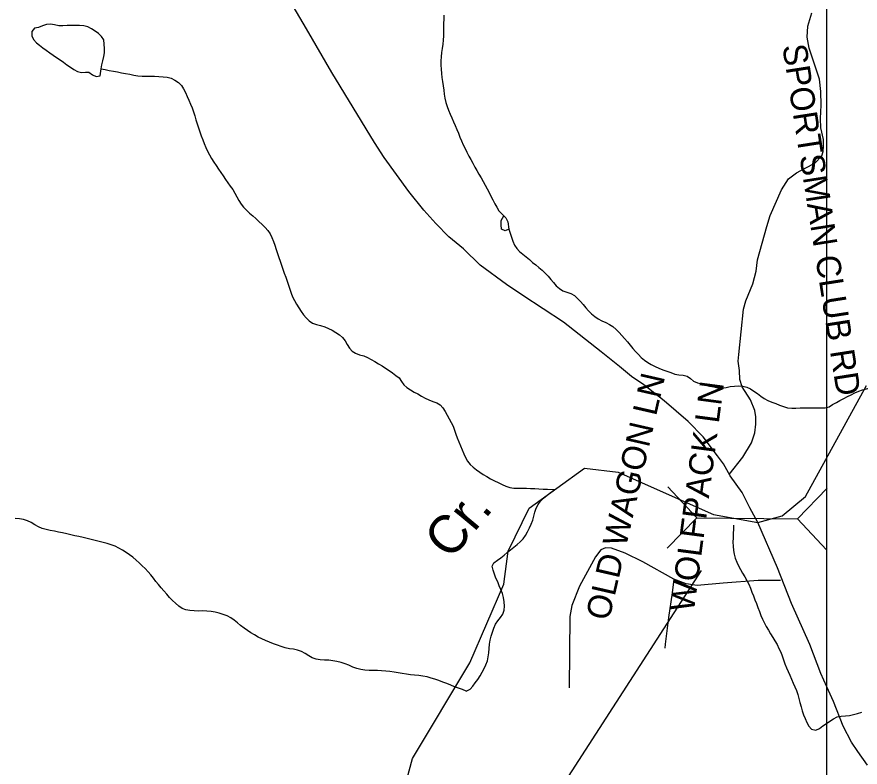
# Model space of a CAD drawing. Extents: x 1950930 to 2061844, y 904556 to 1017002.
# Drawn here: x 1987086 to 1990402, y 964344 to 967294 of the extents above; entities that cross this region are included whole.
import ezdxf

# ---------------------------------------------------------------- set-up
doc = ezdxf.new("R2010")
doc.units = 0
for name, color, linetype in [('Exist Cultural Church Label', 7, 'Continuous'), ('Exist Hydrographic Creek Single Shore', 7, 'Continuous'), ('Exist Hydrographic Creek Single Shore Label', 7, 'Continuous'), ('Exist Hydrographic Misc Water Feature', 7, 'Continuous'), ('Exist Road Non-System Type 51', 7, 'Continuous'), ('Exist Road Non-System Type 51 Label', 7, 'Continuous'), ('Exist Road Primary NC Attributed', 7, 'Continuous'), ('Exist Road Primary NC Structure Culvert Number Label', 7, 'Continuous'), ('Map Preparation Inset Cut Line', 7, 'Continuous')]:
    doc.layers.add(name, color=color, linetype=linetype)

msp = doc.modelspace()

# ---------------------------------------------------------------- linework, layer by layer
at = {"layer": 'Exist Cultural Church Label'}
for p, q in [((1989645.5, 965446.5), (1989758.9, 965324.5)), ((1990271.3, 965440.7), (1990155.7, 965320.9)), ((1989643.3, 965204.7), (1989758.9, 965324.5)), ((1989758.9, 965324.5), (1990155.7, 965320.9)), ((1990269.1, 965198.9), (1990155.7, 965320.9))]:
    msp.add_line(p, q, dxfattribs=at)
at = {"layer": 'Exist Hydrographic Creek Single Shore'}
msp.add_lwpolyline([(1988575.5, 964136.3), (1988641.5, 964377.7), (1988866.4, 964753.8), (1989000.3, 965062.9), (1989017.4, 965193.8), (1989100.4, 965362.7), (1989317.4, 965519), (1989450.4, 965503.1), (1989825.5, 965337.8), (1989998.7, 965305.8), (1990094.9, 965332.7), (1990186.4, 965408.4), (1990426.5, 965844)], dxfattribs=at)
at = {"layer": 'Exist Hydrographic Misc Water Feature'}
for points in [[(1988764.9, 967300.7), (1988764.3, 967284.3), (1988763.9, 967267.9), (1988763.7, 967251.5), (1988763.2, 967235), (1988762.8, 967218.7), (1988762, 967202.3), (1988760.4, 967185.9), (1988758.3, 967169.6), (1988755.9, 967153.2), (1988754, 967136.8), (1988753, 967120.4), (1988753.2, 967104), (1988754, 967087.6), (1988755.5, 967071.1), (1988757.5, 967055.5), (1988759.8, 967039.1), (1988762, 967022.5), (1988764.1, 967006.1), (1988766.3, 966989.6), (1988769, 966974.1), (1988772.7, 966957.5), (1988777.6, 966941.9), (1988783.3, 966927), (1988789.5, 966911.3), (1988796.1, 966896.3), (1988802.6, 966881.5), (1988809.2, 966866.5), (1988815.3, 966850.8), (1988821.9, 966835.8), (1988828.2, 966821), (1988834.6, 966806.1), (1988841.4, 966790.4), (1988848.1, 966775.5), (1988855.7, 966761.4), (1988863.1, 966746.4), (1988870.9, 966732.3), (1988878.7, 966718.3), (1988886.7, 966703.3), (1988894.7, 966689.2), (1988902.9, 966675.1), (1988910.9, 966660.9), (1988918.9, 966646), (1988927.1, 966631.9), (1988934.9, 966617.8), (1988942.5, 966602.8), (1988950, 966588.8), (1988957.4, 966573.8), (1988964.8, 966558.9), (1988972.6, 966544.9), (1988981, 966530.7), (1989000.1, 966511.4)], [(1987416.9, 967089), (1987420.2, 967105.3), (1987423.6, 967120.9), (1987428.4, 967137.2), (1987430.8, 967152.7), (1987430, 967169.2), (1987429.4, 967186.4), (1987427.3, 967202.8), (1987419.3, 967216.1), (1987407.6, 967227.8), (1987394.1, 967238), (1987379.8, 967246.5), (1987365.4, 967254.2), (1987349.6, 967258.6), (1987332.6, 967259.8), (1987316.2, 967260.1), (1987300, 967259.7), (1987283.4, 967259.2), (1987267, 967258.7), (1987250.6, 967259), (1987234.4, 967261.7), (1987218, 967264.6), (1987202, 967264.1), (1987186.6, 967258.7), (1987171.6, 967251.6), (1987154.8, 967248.6), (1987145.2, 967235.8), (1987144.8, 967219.3), (1987151.7, 967204.4), (1987163, 967191.9), (1987175.5, 967181.8), (1987188.4, 967171.6), (1987201.6, 967162.4), (1987215.1, 967152.2), (1987228.6, 967142.9), (1987242, 967133.7), (1987255.9, 967124.4), (1987269.4, 967115), (1987283, 967105.7), (1987296.3, 967095.5), (1987309.8, 967086.2), (1987324.2, 967078.5), (1987340.4, 967075), (1987356.2, 967075.6), (1987369.5, 967076.8), (1987382.8, 967065.9), (1987398, 967059), (1987413.6, 967062), (1987416.9, 967089)], [(1987416.9, 967089), (1987432.9, 967086.2), (1987449.1, 967083.3), (1987465.3, 967080.7), (1987481.3, 967077), (1987497.5, 967074.2), (1987513.5, 967071.4), (1987529.9, 967068.6), (1987545.9, 967065), (1987562.1, 967062.2), (1987578.3, 967060.2), (1987594.4, 967059.9), (1987611.1, 967060.4), (1987627.5, 967060.8), (1987643.9, 967059.7), (1987660.7, 967058.5), (1987677.1, 967056.5), (1987692.5, 967052.1), (1987707.6, 967045.2), (1987721.6, 967035.9), (1987732.9, 967024.2), (1987741.7, 967010.9), (1987749.5, 966996.8), (1987756.2, 966981.1), (1987762.6, 966966.2), (1987768.7, 966950.5), (1987774.9, 966935.5), (1987780.2, 966919.8), (1987785.1, 966904.1), (1987789.9, 966888.4), (1987794.6, 966872.8), (1987799.7, 966857.1), (1987805.4, 966841.4), (1987811, 966826.5), (1987816.7, 966810.7), (1987822.9, 966795.9), (1987829, 966780.2), (1987836, 966765.3), (1987843.2, 966751.2), (1987851.6, 966737), (1987860.4, 966722.9), (1987869.6, 966709.5), (1987878.9, 966695.5), (1987887.9, 966682.2), (1987897.3, 966668.8), (1987906.5, 966654.7), (1987916, 966641.4), (1987925.2, 966628), (1987934.6, 966614.7), (1987943, 966600.6), (1987951.2, 966586.4), (1987959, 966571.5), (1987967.6, 966557.4), (1987977.3, 966544.9), (1987988.8, 966533.2), (1988001.1, 966522.2), (1988013.6, 966511.4), (1988025.7, 966500.4), (1988037.8, 966488.7), (1988050.1, 966477.7), (1988062, 966466), (1988072.6, 966453.5), (1988081.4, 966440.2), (1988088.6, 966426.1), (1988095, 966410.4), (1988100.7, 966395.5), (1988105.6, 966379), (1988110.8, 966363.2), (1988116.1, 966347.5), (1988121.6, 966332.7), (1988127, 966317), (1988132.3, 966301.3), (1988137.6, 966285.6), (1988143.2, 966270.7), (1988148.5, 966255), (1988153.8, 966239.4), (1988158.8, 966223.7), (1988164.1, 966208), (1988170, 966193), (1988177.2, 966178.1), (1988185.4, 966164), (1988194.2, 966149.8), (1988203.2, 966135.7), (1988213.3, 966121.6), (1988224, 966109.9), (1988235.2, 966098.2), (1988248.4, 966089.7), (1988263.7, 966084.4), (1988280.3, 966080.8), (1988296.8, 966075.5), (1988311.5, 966068.6), (1988326.3, 966061.8), (1988340.6, 966053.3), (1988354, 966044), (1988366.3, 966033.1), (1988376.5, 966020.6), (1988385.1, 966005.6), (1988393.9, 965991.5), (1988404.6, 965979.8), (1988417.9, 965971.3)], [(1989020.4, 966458.5), (1989006.2, 966452.2), (1988991.9, 966459.1), (1988990.6, 966476.3), (1988990.4, 966492.8), (1989000.1, 966511.4)], [(1989000.1, 966511.4), (1989009.1, 966503), (1989016.3, 966487.3), (1989020.4, 966458.5)], [(1989020.4, 966458.5), (1989025.7, 966442.8), (1989030.8, 966427.1), (1989036.4, 966411.4), (1989042.7, 966396.5), (1989051.3, 966383.2), (1989062.6, 966371.4), (1989075.1, 966360.5), (1989088.3, 966350.4), (1989101, 966339.5), (1989113.5, 966328.6), (1989126.4, 966318.4), (1989138.9, 966308.4), (1989151.4, 966297.4), (1989163.5, 966286.5), (1989174.8, 966273.9), (1989185.2, 966261.5), (1989195.9, 966248.9), (1989207, 966236.4), (1989218.9, 966225.4), (1989232.6, 966216.9), (1989248.4, 966211.7), (1989264.2, 966206.4), (1989278.1, 966197.9), (1989290.2, 966187.1), (1989301.5, 966175.3), (1989312.6, 966162.9), (1989323.2, 966150.3), (1989334.1, 966137.7), (1989345.6, 966126.1), (1989357.9, 966115.1), (1989371.4, 966106.7), (1989386, 966099), (1989401.4, 966092), (1989415.9, 966084.4), (1989429.7, 966075.9), (1989442, 966065), (1989453.7, 966053.2), (1989464.7, 966041.5), (1989475.6, 966029), (1989486.3, 966015.6), (1989496.9, 966003), (1989507.6, 965990.5), (1989518.2, 965978), (1989529.5, 965966.3), (1989541.2, 965954.5), (1989553.5, 965944.5), (1989566.6, 965934.3), (1989580.4, 965926.6), (1989595.1, 965919), (1989610.3, 965912.1), (1989625.9, 965906), (1989641.5, 965900.8), (1989657.3, 965895.6), (1989672.9, 965889.5), (1989688.6, 965885.8), (1989705.3, 965884.7), (1989721.3, 965881.1), (1989734.4, 965871.8), (1989746.9, 965860.9), (1989761.9, 965854.8), (1989777.6, 965850.5), (1989793.6, 965846), (1989809.6, 965842.4), (1989825.8, 965838.8), (1989842, 965835.1), (1989858, 965834), (1989874.2, 965836.1), (1989890.6, 965839.9), (1989907, 965842), (1989923.2, 965842.5), (1989940.2, 965842.2), (1989955.8, 965837.7), (1989970.2, 965830.8), (1989984.1, 965822.3), (1989997.9, 965813), (1990011.4, 965802.9), (1990024.7, 965793.7), (1990039.1, 965785.2), (1990054, 965779.1), (1990069.8, 965773.8), (1990085, 965767.7), (1990100.6, 965761.7), (1990116.4, 965757.3), (1990132.4, 965755.2), (1990148.8, 965754.9), (1990165.2, 965756.3), (1990181.8, 965756.7), (1990198.2, 965757.2), (1990214.8, 965756.9), (1990231.4, 965756.6), (1990247.8, 965756.1), (1990264, 965756.7), (1990279.6, 965760.5), (1990293.3, 965769.2), (1990308.1, 965777.9), (1990322.3, 965785.8), (1990336.8, 965792.9), (1990351.6, 965800.8), (1990366.1, 965807.9)], [(1988417.9, 965971.3), (1988433.5, 965965.2), (1988449.7, 965960.8), (1988465.1, 965954.7), (1988479.5, 965947.1), (1988493.8, 965938.5), (1988507.8, 965930), (1988521.9, 965921.5), (1988535.6, 965912.3), (1988549.4, 965903.8), (1988563.1, 965893.6), (1988576.2, 965884.3), (1988588.7, 965874.2), (1988598, 965860.8), (1988607.2, 965846.8), (1988619.5, 965836.7), (1988633.4, 965827.4), (1988647.8, 965818.8), (1988662.2, 965811.2), (1988676.5, 965802.7), (1988690.9, 965795), (1988705.6, 965788.1), (1988721.6, 965782.1), (1988737.2, 965776.9), (1988750.9, 965768.3), (1988761.4, 965756.7), (1988769.6, 965742.5), (1988777.4, 965727.5), (1988786, 965713.4), (1988794.2, 965699.3), (1988801.4, 965684.4), (1988806.9, 965668.7), (1988812.3, 965653), (1988817.8, 965638.1), (1988824.1, 965622.4), (1988830.5, 965607.5), (1988836.7, 965591.7), (1988843, 965576), (1988850, 965561.1), (1988858.4, 965547), (1988868.6, 965534.5), (1988880.3, 965523.5), (1988892.8, 965513.5), (1988906, 965504.1), (1988919.9, 965494.9), (1988934.3, 965486.4), (1988948.8, 965477.9), (1988963.8, 965470.2), (1988978.3, 965462.5), (1988993.5, 965455.6), (1989008.3, 965448.8), (1989023.7, 965443.4), (1989039.9, 965441.5), (1989056.5, 965441.2), (1989073.3, 965440.8), (1989089.9, 965440.5), (1989106.1, 965439.3), (1989122.5, 965439), (1989138.9, 965437.8), (1989155.5, 965437.5), (1989171.7, 965437.1), (1989201, 965435.7)], [(1990366.1, 965807.9), (1990380.9, 965815), (1990395.9, 965822), (1990411.3, 965827.4), (1990427.2, 965831.2), (1990445.9, 965836.5)], [(1988852.9, 964642.9), (1988868, 964650.8), (1988879.1, 964662.1), (1988888.5, 964675), (1988897.8, 964688.7), (1988907, 964703.3), (1988915.4, 964717.1), (1988923.4, 964731.7), (1988930.2, 964746.4), (1988936.1, 964761.8), (1988939.4, 964777.3), (1988941.4, 964793.7), (1988942.7, 964810.1), (1988944.1, 964827.3), (1988946.8, 964842.8), (1988951.1, 964859.1), (1988955.8, 964874.6), (1988961.7, 964890.1), (1988968.1, 964905.6), (1988977.1, 964919.3), (1988987.6, 964932.2), (1988996.6, 964946), (1989001.5, 964960.6), (1989002.7, 964977.1), (1989001.7, 964994.3), (1988999.5, 965010.8), (1988995.4, 965026.4), (1988989.4, 965042.2), (1988982.9, 965057), (1988976.5, 965072), (1988969.7, 965086.9), (1988963.6, 965102.6), (1988958.3, 965118.3), (1988954.8, 965134.8), (1988961.5, 965147.8), (1988976.1, 965157.3), (1988989.2, 965167.6), (1989001.7, 965178.1), (1989014.2, 965188.5), (1989026.7, 965198.9), (1989039.7, 965209.3), (1989053, 965219.6), (1989065.5, 965230.1), (1989076.8, 965241.4), (1989086.2, 965255.1), (1989094.2, 965268.9), (1989101.4, 965284.3), (1989107.9, 965299), (1989114.1, 965314.5), (1989118.6, 965330.8), (1989123.1, 965347.1), (1989128.2, 965362.6), (1989135.4, 965376.4), (1989145.3, 965389.3), (1989156.7, 965401.4), (1989169.5, 965411.8), (1989182.4, 965422.1), (1989201, 965435.7)], [(1987393.9, 965235.1), (1987377.7, 965238.8), (1987361.9, 965243.2), (1987346.1, 965246.8), (1987329.7, 965250.5), (1987313.9, 965254.1), (1987298.1, 965257.7), (1987282, 965261.3), (1987266, 965264.9), (1987249.8, 965268.5), (1987233.8, 965271.3), (1987217.4, 965274.1), (1987201.4, 965277.8), (1987185.8, 965282.2), (1987170.6, 965288.2), (1987156.5, 965296.7), (1987142.5, 965306.1), (1987128, 965312.9), (1987112.2, 965317.3), (1987096, 965320.1), (1987079.8, 965322.1)], [(1989903.1, 965295.6), (1989903.1, 965279.2), (1989902.7, 965262.8), (1989902.1, 965245.7), (1989901.5, 965229.2), (1989901.9, 965212.8), (1989903.1, 965196.4), (1989906, 965180.8), (1989910.3, 965165.1), (1989916.3, 965150.1), (1989923.2, 965135.2), (1989931.2, 965121.1), (1989939.4, 965106.1), (1989947.8, 965092.1), (1989955.8, 965077.9), (1989963.4, 965063), (1989970, 965048.1), (1989976.3, 965032.3), (1989982.3, 965017.4), (1989988, 965001.8), (1989993.8, 964986.9), (1989999.5, 964971.2), (1990005.5, 964956.3), (1990011.6, 964940.7), (1990018.2, 964925.7), (1990025.1, 964910.8), (1990032.5, 964896.7), (1990040.7, 964882.5), (1990049.5, 964868.4), (1990058.2, 964854.3), (1990066.8, 964840.2), (1990075, 964826), (1990082.3, 964811.1), (1990089.1, 964796.2), (1990094.9, 964781.3), (1990100.4, 964765.6), (1990105.7, 964750), (1990111.9, 964735.1), (1990118.2, 964720.1), (1990125.2, 964705.3), (1990132, 964690.3), (1990138.9, 964674.5), (1990145.3, 964659.6), (1990151.4, 964644.8), (1990156.6, 964629.1), (1990161.1, 964613.4), (1990165, 964597.7), (1990169.3, 964581.2), (1990173.8, 964565.5), (1990179.1, 964549.8), (1990185.5, 964535), (1990192.3, 964519.3), (1990200.3, 964505.1), (1990210.7, 964493.4), (1990227.3, 964489.7), (1990241.5, 964496), (1990255.2, 964506.5), (1990268.9, 964516), (1990282.9, 964524.7), (1990296.6, 964534.2), (1990311, 964541.3), (1990326.8, 964545.2), (1990343.4, 964545.6), (1990359.8, 964547.8), (1990376, 964551.6), (1990391.8, 964555.3), (1990407.8, 964559.9)], [(1988852.9, 964642.9), (1988837.7, 964649.1), (1988822.3, 964655.1), (1988806.9, 964660.2), (1988791.7, 964666.3), (1988776.4, 964672.4), (1988761, 964678.5), (1988745.6, 964684.5), (1988730, 964689.8), (1988714.6, 964694.2), (1988698.9, 964698.7), (1988682.7, 964702.3), (1988666.7, 964704.2), (1988649.9, 964705.4), (1988633.7, 964707.4), (1988617.5, 964709.4), (1988601.3, 964712.1), (1988584.9, 964715), (1988568.9, 964717.8), (1988552.7, 964719.7), (1988536.3, 964721.8), (1988519.9, 964722.9), (1988503.7, 964724), (1988487, 964724.3), (1988470.6, 964724.7), (1988454.2, 964725.9), (1988438, 964727.8), (1988422.2, 964732.3), (1988406.9, 964737.6), (1988391.7, 964744.4), (1988376.3, 964750.5), (1988360.5, 964754.9), (1988344.7, 964759.3), (1988328.5, 964762.1), (1988312.1, 964764.1), (1988295.5, 964765.2), (1988279.1, 964766.4), (1988263.1, 964769.2), (1988247.7, 964773.6), (1988233.4, 964781.2), (1988219.2, 964790.6), (1988204.9, 964799.2), (1988189.7, 964804.3), (1988173.7, 964808), (1988157.5, 964809.9), (1988141.3, 964813.6), (1988125.5, 964817.9), (1988110.2, 964823.3), (1988094.8, 964829.3), (1988079.4, 964835.4), (1988064, 964841.4), (1988049.1, 964848.3), (1988034.5, 964855.1), (1988020.1, 964863.7), (1988006, 964872.2), (1987992.3, 964881.5), (1987979.1, 964890.7), (1987965.8, 964900.9), (1987953.5, 964911.8), (1987940.8, 964921.9), (1987927.7, 964931.2), (1987912.9, 964938.9), (1987897.7, 964944.1), (1987881.7, 964949.4), (1987865.7, 964953.1), (1987849.5, 964955.7), (1987832.9, 964957), (1987816.3, 964958.2), (1987799.5, 964957.7), (1987783.1, 964958.8), (1987766.7, 964959.9), (1987750.9, 964962.8), (1987736.1, 964968), (1987722.6, 964977.3), (1987709.9, 964989), (1987697.6, 964999.9), (1987686.1, 965011.7), (1987675, 965024.2), (1987664.4, 965036.8), (1987653.9, 965049.2), (1987643.3, 965061.8), (1987633, 965074.3), (1987623, 965087.7), (1987612.3, 965100.2), (1987601.6, 965111.9), (1987590.1, 965124.5), (1987578.7, 965135.4), (1987566.8, 965147), (1987554.5, 965158), (1987542, 965169), (1987529, 965179), (1987515.7, 965188.4), (1987501.8, 965196.9), (1987487.2, 965205.4), (1987472.2, 965212.2), (1987457.3, 965218.3), (1987441.5, 965222.7), (1987425.9, 965227.1), (1987409.9, 965231.6), (1987393.9, 965235.1)]]:
    msp.add_lwpolyline(points, dxfattribs=at)
at = {"layer": 'Exist Road Non-System Type 51'}
for points in [[(1989886.4, 965494.2), (1989940.1, 965563.2), (1989974.8, 965619.7), (1989988, 965658.8), (1989991.2, 965692), (1989992, 965721.2), (1989987.2, 965746.4), (1989970, 965787.6), (1989937.1, 965839.8), (1989929.2, 965868.2), (1989926.6, 965902.8), (1989922.6, 965940.6), (1989924.6, 965966.6), (1989942.9, 966144.1), (1989951.5, 966177.3), (1989979.6, 966244.7), (1989993, 966294.5), (1989998.2, 966338.3), (1990035.1, 966470.1), (1990047.8, 966513.2), (1990092.5, 966613.8), (1990120.4, 966656.3), (1990151.6, 966680.2), (1990185.5, 966699.4), (1990223.4, 966718.7), (1990250.9, 966746.9), (1990256.1, 966764.2), (1990257.5, 966786.1), (1990256.9, 966811.3), (1990246.4, 966856.9), (1990245.8, 966894.4), (1990248.9, 966946), (1990246.8, 966999.8), (1990241.9, 967049.2), (1990200.5, 967170.2), (1990193, 967214.4), (1990196.2, 967257.4), (1990211.2, 967309)], [(1989669.2, 965083.6), (1989547.8, 965150.8), (1989477.2, 965184.7), (1989424.4, 965204.9), (1989400.5, 965206.1), (1989381.6, 965198.6), (1989361.5, 965170.9), (1989298.5, 965055.1), (1989268.4, 964979.6), (1989260.8, 964936.8), (1989257, 964656.1)], [(1989669.2, 965083.6), (1989662.2, 965029.9), (1989648.5, 964933), (1989634.6, 964827.2), (1989633.4, 964811.9)], [(1990088.6, 965077.7), (1990000, 965077.7), (1989862.5, 965066.9), (1989760.4, 965057.9), (1989717.8, 965065.1), (1989669.2, 965083.6)]]:
    msp.add_lwpolyline(points, dxfattribs=at)
at = {"layer": 'Exist Road Primary NC Attributed'}
msp.add_lwpolyline([(1990430.4, 964351.9), (1990391.9, 964406), (1990367.2, 964442.3), (1990335.1, 964505.2), (1990297.3, 964601.7), (1990270.8, 964660.5), (1990247.6, 964711.8), (1990203.2, 964825.7), (1990132.2, 964987.1), (1990076.3, 965128), (1989998.7, 965305.8), (1989967.9, 965364), (1989938.1, 965423.8), (1989890.3, 965488.7), (1989864.1, 965536.6), (1989841.3, 965568.6), (1989784, 965642.5), (1989725.3, 965702.8), (1989631.6, 965784.2), (1989551.4, 965846.8), (1989502, 965879.2), (1989455.7, 965919.4), (1989383.9, 965977.3), (1989235, 966093.9), (1989075.3, 966198.2), (1989010.5, 966241.4), (1988907.1, 966317.1), (1988841.5, 966381.2), (1988784.4, 966429.1), (1988733.4, 966481.6), (1988685.6, 966534.1), (1988627.7, 966607.5), (1988530.5, 966740.3), (1988492.7, 966799.8), (1988324.5, 967074.7), (1988224.9, 967246.9), (1988116.1, 967433.1)], dxfattribs=at)
at = {"layer": 'Exist Road Primary NC Structure Culvert Number Label'}
msp.add_line((1989776.1, 965117), (1988483.6, 963114.1), dxfattribs=at)
at = {"layer": 'Map Preparation Inset Cut Line'}
for p, q in [((1990270.8, 966752.9), (1990270.8, 967395.3)), ((1990270.8, 964660.5), (1990270.8, 966752.9)), ((1990270.8, 961097.2), (1990270.8, 964660.5))]:
    msp.add_line(p, q, dxfattribs=at)

# ---------------------------------------------------------------- texts
at = {"layer": 'Exist Hydrographic Creek Single Shore Label'}
msp.add_text('Cr.', height=150, rotation=50.209, dxfattribs=at).set_placement((1988791.4, 965154.4))
msp.add_text('Cr.', height=150, rotation=50.209, dxfattribs=at).set_placement((1988791.4, 965154.4))
msp.add_text('Cr.', height=150, rotation=50.209, dxfattribs=at).set_placement((1988791.4, 965154.4))
at = {"layer": 'Exist Road Non-System Type 51 Label'}
for s, rotation, p in [('  SPORTSMAN CLUB RD', 278.8854, (1990084.4, 967249.1)), ('  OLD WAGON LN', 77.0816, (1989398.6, 964847.8)), ('  WOLFPACK LN', 82.4793, (1989738.4, 964881.3))]:
    msp.add_text(s, height=95, rotation=rotation, dxfattribs=at).set_placement(p)

doc.saveas('drawing.dxf')
